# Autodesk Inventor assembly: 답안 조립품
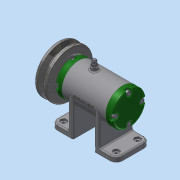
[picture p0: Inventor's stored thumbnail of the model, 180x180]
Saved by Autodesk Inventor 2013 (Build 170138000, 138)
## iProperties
Created: 2017-02
Part Number: 답안 조립품
Document SubType Name: Assembly
Designer: dgall
Author: dgall
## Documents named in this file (16)
- C:\Users\dgall\Desktop\470207V1032\답안 조립품.iam
- C:\Users\dgall\Desktop\470207V1032\본체.ipt
- C:\Users\dgall\Desktop\470207V1032\V벨트풀리.ipt
- C:\Users\dgall\Desktop\470207V1032\너트 M 8.ipt
- C:\Users\dgall\Desktop\470207V1032\니플 M 6 x 0.75.ipt
- C:\Users\dgall\Desktop\470207V1032\뒤커버.ipt
- C:\Users\dgall\Desktop\470207V1032\베어링 15 x 32 x 9.ipt
- C:\Users\dgall\Desktop\470207V1032\볼트 M 6 x 8.ipt
- C:\Users\dgall\Desktop\470207V1032\볼트 M4 x 12.ipt
- C:\Users\dgall\Desktop\470207V1032\스프링와셔 8.ipt
- C:\Users\dgall\Desktop\470207V1032\앞커버.ipt
- C:\Users\dgall\Desktop\470207V1032\오일 실 15 25 7.ipt
- C:\Users\dgall\Desktop\470207V1032\와셔 6x11.5.ipt
- C:\Users\dgall\Desktop\470207V1032\와셔 8x17.ipt
- C:\Users\dgall\Desktop\470207V1032\축.ipt
- C:\Users\dgall\Desktop\470207V1032\키 3 x 3 x 12.ipt
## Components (11 placed, 3 different names)
1. V벨트풀리:1
2. KS B 2023 6002 - 15 x 32 x 9:1
3. ISO 4762 M4 x 12:1
4. KS B 2023 6002 - 15 x 32 x 9:2
5. ISO 4762 M4 x 12:2
6. ISO 4762 M4 x 12:3
7. ISO 4762 M4 x 12:4
8. ISO 4762 M4 x 12:5
9. ISO 4762 M4 x 12:6
10. ISO 4762 M4 x 12:7
11. ISO 4762 M4 x 12:8
